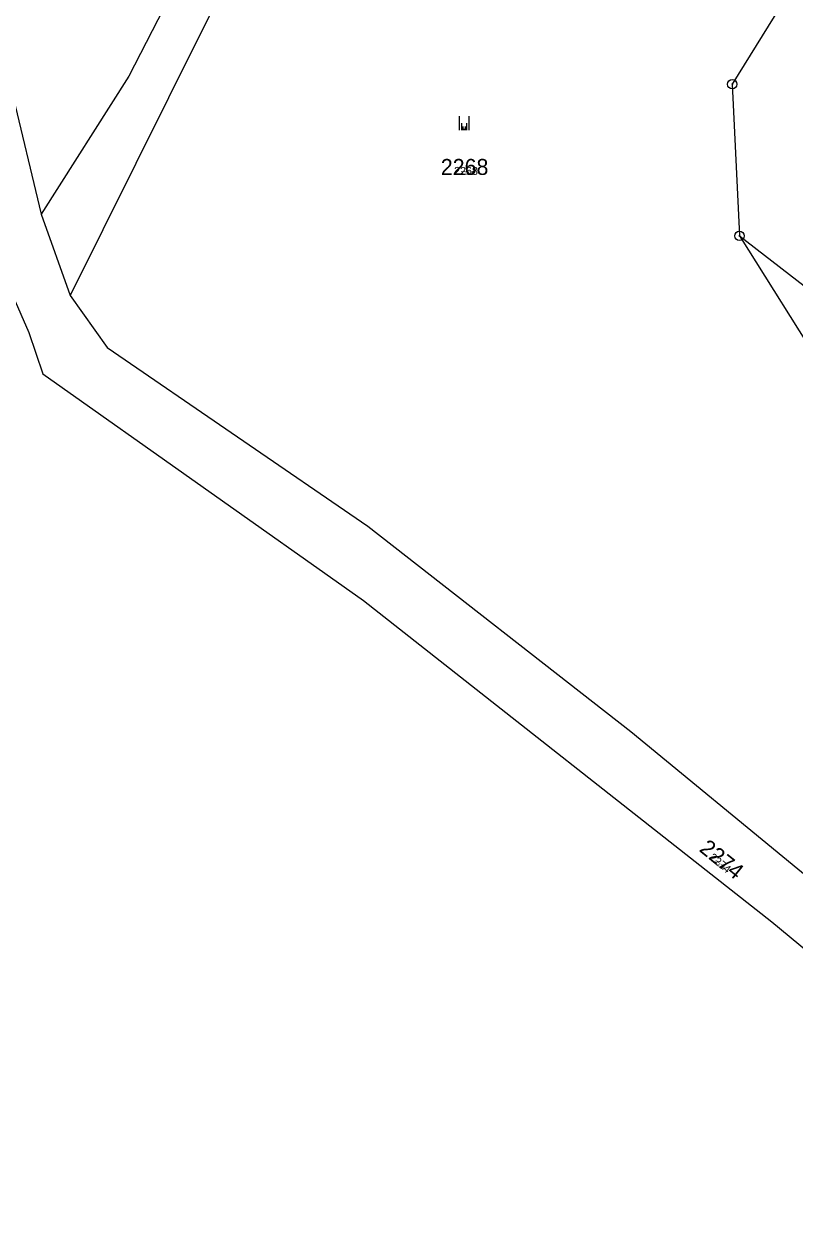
# Model space of a CAD drawing. Extents: x -744652 to -739090, y -980828 to -975855.
# Drawn here: x -742116.9 to -742035.1, y -979035.7 to -978907.9 of the extents above; entities that cross this region are included whole.
import ezdxf

# ---------------------------------------------------------------- set-up
doc = ezdxf.new("R2010")
doc.units = 0
for name, color, linetype in [('KAT_02_hranice parcel', 7, 'Continuous'), ('KAT_03_1000_čísla parcelní', 7, 'Continuous'), ('KAT_03_100_čísla parcelní', 7, 'Continuous'), ('KAT_03_250_čísla parcelní', 7, 'Continuous'), ('KAT_03_500_čísla parcelní', 7, 'Continuous'), ('KAT_05_1000_značky kultur', 7, 'Continuous'), ('KAT_05_100_značky kultur', 7, 'Continuous'), ('KAT_05_250_značky kultur', 7, 'Continuous'), ('KAT_05_500_značky kultur', 7, 'Continuous'), ('KAT_11_značky bodu BP', 7, 'Continuous')]:
    doc.layers.add(name, color=color, linetype=linetype)

msp = doc.modelspace()

# ---------------------------------------------------------------- linework, layer by layer
at = {"layer": 'KAT_02_hranice parcel'}
for p, q in [((-742115.08, -978928.14), (-742112, -978936.77)), ((-742040.95, -978930.44), (-741921.59, -979022.81))]:
    msp.add_line(p, q, dxfattribs=at)
for points in [[(-742072.77, -978862.78), (-742085.1, -978882.72), (-742101.55, -978915.77), (-742112, -978936.77)], [(-742165.38, -978864.69), (-742164.73, -978869.27), (-742160.26, -978877.21), (-742157.81, -978879.11), (-742152.42, -978883.29), (-742151.92, -978884.21), (-742121.08, -978910.35), (-742118.23, -978914.94), (-742115.08, -978928.14)], [(-742022.64, -978880.15), (-742032.62, -978899.61), (-742041.71, -978914.32), (-742040.95, -978930.44)], [(-742091.53, -978885.78), (-742105.78, -978913.48), (-742115.08, -978928.14)], [(-742040.95, -978930.44), (-742031.92, -978944.81), (-742018.49, -978966.16), (-742016.3, -978984.87), (-742009.54, -979001.53), (-742002.99, -979010.39), (-741997.13, -979014.66), (-741990.94, -979020.83), (-741987.5, -979026.9), (-741982.8, -979035.03), (-741981.47, -979038.94)], [(-742118.7, -978935.43), (-742116.39, -978940.69), (-742114.89, -978945.1), (-742080.84, -978969.18), (-742037.5, -979003.3), (-741997.77, -979036.21), (-741988.62, -979042.39), (-741979.98, -979046.43), (-741966.12, -979050.79), (-741960.33, -979052.29), (-741948.26, -979056.48)], [(-742112, -978936.77), (-742108.07, -978942.28), (-742080.41, -978961.27), (-742052.47, -978983.1), (-742017.01, -979012.25), (-741995.77, -979030.11), (-741991.61, -979033.37), (-741981.47, -979038.94)]]:
    msp.add_lwpolyline(points, dxfattribs=at)
at = {"layer": 'KAT_05_1000_značky kultur'}
for p, q in [((-742070.65, -978919.2), (-742070.65, -978917.7)), ((-742069.65, -978919.2), (-742069.65, -978917.7))]:
    msp.add_line(p, q, dxfattribs=at)
at = {"layer": 'KAT_05_100_značky kultur'}
for p, q in [((-742070.19, -978919.2), (-742070.19, -978919.05)), ((-742070.09, -978919.2), (-742070.09, -978919.05))]:
    msp.add_line(p, q, dxfattribs=at)
at = {"layer": 'KAT_05_250_značky kultur'}
for p, q in [((-742070.27, -978919.2), (-742070.27, -978918.83)), ((-742070.02, -978919.2), (-742070.02, -978918.83))]:
    msp.add_line(p, q, dxfattribs=at)
at = {"layer": 'KAT_05_500_značky kultur'}
for p, q in [((-742070.4, -978919.2), (-742070.4, -978918.45)), ((-742069.9, -978919.2), (-742069.9, -978918.45))]:
    msp.add_line(p, q, dxfattribs=at)
at = {"layer": 'KAT_11_značky bodu BP'}
for centre, radius in [((-742041.71, -978914.32), 0.5), ((-742041.71, -978914.32), 0.0303), ((-742040.95, -978930.44), 0.5), ((-742040.95, -978930.44), 0.0303)]:
    msp.add_circle(centre, radius, dxfattribs=at)

# ---------------------------------------------------------------- texts
at = {"layer": 'KAT_03_1000_čísla parcelní'}
msp.add_text('2268', height=1.7, dxfattribs=at).set_placement((-742072.65, -978923.96))
msp.add_text('2274', height=1.7, rotation=321, dxfattribs=at).set_placement((-742045.31, -978995.73))
at = {"layer": 'KAT_03_100_čísla parcelní'}
msp.add_text('2268', height=0.17, dxfattribs=at).set_placement((-742070.12, -978923.96))
msp.add_text('2274', height=0.17, rotation=321, dxfattribs=at).set_placement((-742043.39, -978997.29))
at = {"layer": 'KAT_03_250_čísla parcelní'}
msp.add_text('2268', height=0.425, dxfattribs=at).set_placement((-742070.54, -978923.96))
msp.add_text('2274', height=0.425, rotation=321, dxfattribs=at).set_placement((-742043.71, -978997.03))
at = {"layer": 'KAT_03_500_čísla parcelní'}
msp.add_text('2268', height=0.85, dxfattribs=at).set_placement((-742071.24, -978923.96))
msp.add_text('2274', height=0.85, rotation=321, dxfattribs=at).set_placement((-742044.24, -978996.6))

doc.saveas('drawing.dxf')
